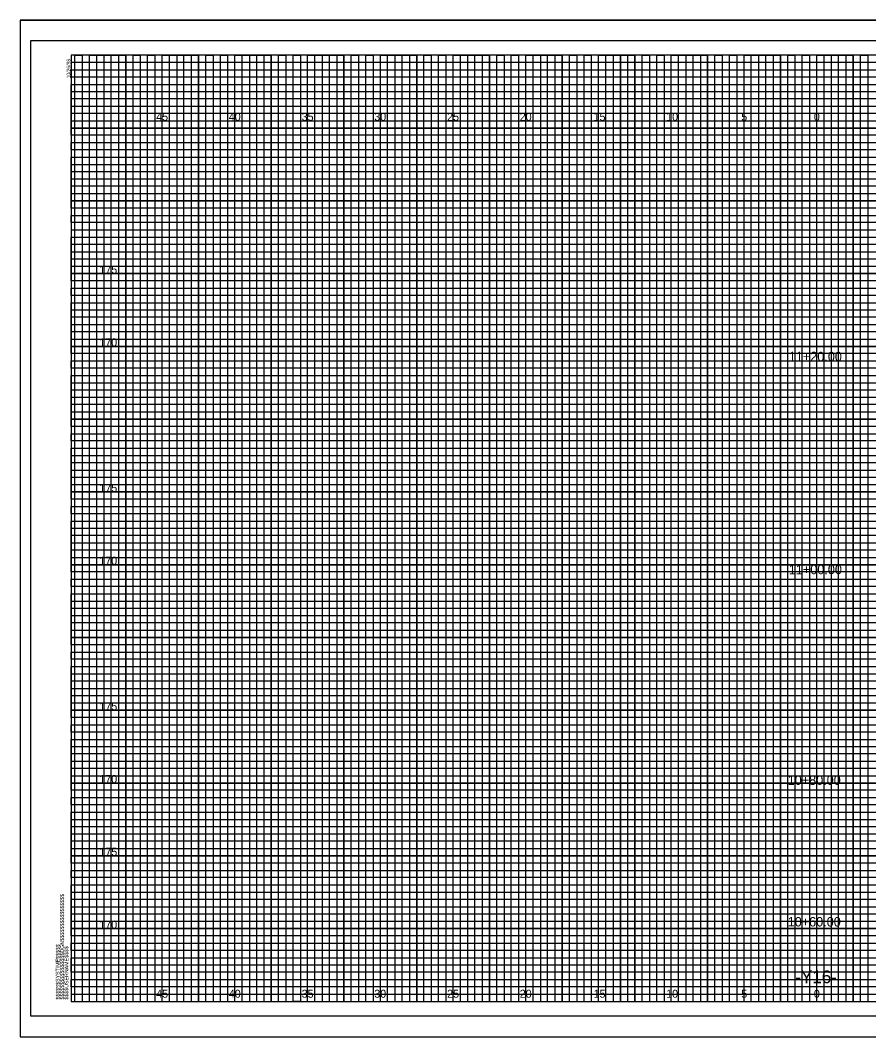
# Model space of a CAD drawing. Extents: x -4 to 103, y -2 to 67.
# Drawn here: x -3.5 to 54.8, y -2.4 to 67.4 of the extents above; entities that cross this region are included whole.
import ezdxf

# ---------------------------------------------------------------- set-up
doc = ezdxf.new("R2010")
doc.units = 0
for name, color, linetype in [('Exist XS Ground Line', 7, 'Continuous'), ('Old_Level_10', 7, 'Continuous'), ('Old_Level_16', 7, 'Continuous'), ('Old_Level_3', 7, 'Continuous'), ('Old_Level_5', 7, 'Continuous'), ('Old_Level_8', 7, 'Continuous'), ('Prop XS Dump Level', 7, 'Continuous'), ('Prop XS EOT Tick Mark', 7, 'Continuous'), ('Prop XS Finish Grade', 7, 'Continuous'), ('Prop XS Side Slope Text', 7, 'Continuous'), ('Prop XS Suitable Common Exc Shape', 7, 'Continuous')]:
    doc.layers.add(name, color=color, linetype=linetype)

msp = doc.modelspace()

# ---------------------------------------------------------------- linework, layer by layer
at = {"layer": 'Exist XS Ground Line'}
msp.add_lwpolyline([(103, 66), (-2.8, 66), (-2.8, -1), (103, -1)], close=True, dxfattribs=at)
at = {"layer": 'Old_Level_10'}
for p, q in [((1.25, 0), (1.25, 65)), ((3.75, 0), (3.75, 65)), ((6.25, 0), (6.25, 65)), ((8.75, 0), (8.75, 65)), ((11.25, 0), (11.25, 65)), ((13.75, 0), (13.75, 65)), ((16.25, 0), (16.25, 65)), ((18.75, 0), (18.75, 65)), ((21.25, 0), (21.25, 65)), ((23.75, 0), (23.75, 65)), ((26.25, 0), (26.25, 65)), ((28.75, 0), (28.75, 65)), ((31.25, 0), (31.25, 65)), ((33.75, 0), (33.75, 65)), ((36.25, 0), (36.25, 65)), ((38.75, 0), (38.75, 65)), ((41.25, 0), (41.25, 65)), ((43.75, 0), (43.75, 65)), ((46.25, 0), (46.25, 65)), ((48.75, 0), (48.75, 65)), ((51.25, 0), (51.25, 65)), ((53.75, 0), (53.75, 65)), ((0, 62.5), (74.25, 62.5)), ((0, 60), (102.5, 60)), ((0, 57.5), (102.5, 57.5)), ((0, 55), (102.5, 55)), ((0, 52.5), (102.5, 52.5)), ((0, 50), (102.5, 50)), ((0, 47.5), (102.5, 47.5)), ((0, 45), (102.5, 45)), ((0, 42.5), (102.5, 42.5)), ((0, 40), (102.5, 40)), ((0, 37.5), (102.5, 37.5)), ((0, 35), (102.5, 35)), ((0, 32.5), (102.5, 32.5)), ((0, 30), (102.5, 30)), ((0, 27.5), (102.5, 27.5)), ((0, 25), (102.5, 25)), ((0, 22.5), (102.5, 22.5)), ((0, 20), (102.5, 20)), ((0, 17.5), (102.5, 17.5)), ((0, 15), (102.5, 15)), ((0, 12.5), (102.5, 12.5)), ((0, 10), (102.5, 10)), ((0, 7.5), (102.5, 7.5)), ((0, 5), (102.5, 5)), ((0, 2.5), (102.5, 2.5))]:
    msp.add_line(p, q, dxfattribs=at)
at = {"layer": 'Old_Level_3'}
for p, q in [((-3.5, 67.4), (103.4, 67.4)), ((-3.5, 67.4), (-3.5, -2.425)), ((-3.5, -2.425), (102.1625, -2.425))]:
    msp.add_line(p, q, dxfattribs=at)
at = {"layer": 'Old_Level_5'}
msp.add_lwpolyline([(103.4, 67.4), (-3.5, 67.4), (-3.5, -2.425), (103.4, -2.425)], close=True, dxfattribs=at)
at = {"layer": 'Old_Level_8'}
for points in [[(1.25, 0), (1.25, 65), (3.75, 65), (3.75, 0), (6.25, 0), (6.25, 65), (8.75, 65), (8.75, 0), (11.25, 0), (11.25, 65), (13.75, 65), (13.75, 0), (16.25, 0), (16.25, 65), (18.75, 65), (18.75, 0), (21.25, 0), (21.25, 65), (23.75, 65), (23.75, 0), (26.25, 0), (26.25, 65), (28.75, 65), (28.75, 0), (31.25, 0), (31.25, 65), (33.75, 65), (33.75, 0), (36.25, 0), (36.25, 65), (38.75, 65), (38.75, 0), (41.25, 0), (41.25, 65), (43.75, 65), (43.75, 0), (46.25, 0), (46.25, 65), (48.75, 65), (48.75, 0), (51.25, 0), (51.25, 65), (53.75, 65), (53.75, 0)], [(102.5, 60), (0, 60), (0, 62.5), (74.25, 62.5)], [(102.5, 55), (0, 55), (0, 57.5), (102.5, 57.5)], [(102.5, 50), (0, 50), (0, 52.5), (102.5, 52.5)], [(102.5, 45), (0, 45), (0, 47.5), (102.5, 47.5)], [(102.5, 40), (0, 40), (0, 42.5), (102.5, 42.5)], [(102.5, 35), (0, 35), (0, 37.5), (102.5, 37.5)], [(102.5, 30), (0, 30), (0, 32.5), (102.5, 32.5)], [(102.5, 25), (0, 25), (0, 27.5), (102.5, 27.5)], [(102.5, 20), (0, 20), (0, 22.5), (102.5, 22.5)], [(102.5, 15), (0, 15), (0, 17.5), (102.5, 17.5)], [(102.5, 10), (0, 10), (0, 12.5), (102.5, 12.5)], [(102.5, 5), (0, 5), (0, 7.5), (102.5, 7.5)], [(0, 2.5), (102.5, 2.5)]]:
    msp.add_lwpolyline(points, dxfattribs=at)
at = {"layer": 'Prop XS Dump Level'}
for p, q in [((0, 0), (0, 0)), ((0, 0), (0, 0)), ((-3.5, -2.425), (103.4, -2.425))]:
    msp.add_line(p, q, dxfattribs=at)
msp.add_lwpolyline([(102.5, 65), (0, 65), (0, 0), (102.5, 0)], close=True, dxfattribs=at)
at = {"layer": 'Prop XS Finish Grade'}
for points in [[(0.25, 0), (0.25, 65), (0.75, 65), (0.75, 0), (1.75, 0), (1.75, 65), (2.25, 65), (2.25, 0), (2.75, 0), (2.75, 65), (3.25, 65), (3.25, 0), (4.25, 0), (4.25, 65), (4.75, 65), (4.75, 0), (5.25, 0), (5.25, 65), (5.75, 65), (5.75, 0), (6.75, 0), (6.75, 65), (7.25, 65), (7.25, 0), (7.75, 0), (7.75, 65), (8.25, 65), (8.25, 0), (9.25, 0), (9.25, 65), (9.75, 65), (9.75, 0), (10.25, 0), (10.25, 65), (10.75, 65), (10.75, 0), (11.75, 0), (11.75, 65), (12.25, 65), (12.25, 0), (12.75, 0), (12.75, 65), (13.25, 65), (13.25, 0), (14.25, 0), (14.25, 65), (14.75, 65), (14.75, 0), (15.75, 0), (15.25, 0), (15.25, 65), (15.75, 65), (15.75, 0), (16.75, 0), (16.75, 65), (17.25, 65), (17.25, 0), (17.75, 0), (17.75, 65), (18.25, 65), (18.25, 0), (19.25, 0), (19.25, 65), (19.75, 65), (19.75, 0), (20.25, 0), (20.25, 65), (20.75, 65), (20.75, 0), (21.75, 0), (21.75, 65), (22.25, 65), (22.25, 0), (22.75, 0), (22.75, 65), (23.25, 65), (23.25, 0), (24.25, 0), (24.25, 65), (24.75, 65), (24.75, 0), (25.25, 0), (25.25, 65), (25.75, 65), (25.75, 0), (26.75, 0), (26.75, 65), (27.25, 65), (27.25, 0), (27.75, 0), (27.75, 65), (28.25, 65), (28.25, 0), (29.25, 0), (29.25, 65), (29.75, 65), (29.75, 0), (30.25, 0), (30.25, 65), (30.75, 65), (30.75, 0)], [(30.75, 0), (31.75, 0), (31.75, 65), (32.25, 65), (32.25, 0), (32.75, 0), (32.75, 65), (33.25, 65), (33.25, 0), (34.25, 0), (34.25, 65), (34.75, 65), (34.75, 0), (35.25, 0), (35.25, 65), (35.75, 65), (35.75, 0), (36.75, 0), (36.75, 65), (37.25, 65), (37.25, 0), (37.75, 0), (37.75, 65), (37.75, 0)], [(38.25, 65), (38.25, 0), (39.25, 0), (39.25, 65), (39.75, 65), (39.75, 0), (40.25, 0), (40.25, 65), (40.75, 65), (40.75, 0), (41.75, 0), (41.75, 65), (42.25, 65), (42.25, 0), (42.75, 0), (42.75, 65), (43.25, 65), (43.25, 0), (43.75, 0), (44.25, 0), (44.25, 65), (44.75, 65), (44.75, 0), (45.25, 0), (45.25, 65), (45.75, 65), (45.75, 0), (46.75, 0), (46.75, 65), (47.25, 65), (47.25, 0), (47.75, 0), (47.75, 65), (48.25, 65), (48.25, 0), (49.25, 0), (49.25, 65), (49.75, 65), (49.75, 0), (50.25, 0), (50.25, 65), (50.75, 65), (50.75, 0), (51.75, 0), (51.75, 65), (52.25, 65), (52.25, 0), (52.75, 0), (52.75, 65), (53.25, 65), (53.25, 0), (54.25, 0), (54.25, 65), (54.75, 65), (54.75, 0), (55.25, 0)], [(0, 62), (0, 63), (74.25, 63), (74.25, 63.5), (0, 63.5), (0, 64), (74.25, 64), (74.25, 64.5), (0, 64.5)], [(102.5, 62), (0, 62)], [(102.5, 61), (0, 61), (0, 61.5), (102.5, 61.5)], [(102.5, 59.5), (0, 59.5), (0, 60.5), (102.5, 60.5)], [(102.5, 58.5), (0, 58.5), (0, 59), (102.5, 59)], [(102.5, 57), (0, 57), (0, 58), (102.5, 58)], [(102.5, 56), (0, 56), (0, 56.5), (102.5, 56.5)], [(102.5, 54.5), (0, 54.5), (0, 55.5), (102.5, 55.5)], [(102.5, 53.5), (0, 53.5), (0, 54), (102.5, 54)], [(0, 53), (102.5, 53)], [(102.5, 52), (0, 52)], [(102.5, 51), (0, 51), (0, 51.5), (102.5, 51.5)], [(102.5, 49.5), (0, 49.5), (0, 50.5), (102.5, 50.5)], [(102.5, 48.5), (0, 48.5), (0, 49), (102.5, 49)], [(102.5, 47), (0, 47), (0, 48), (102.5, 48)], [(102.5, 46), (0, 46), (0, 46.5), (102.5, 46.5)], [(102.5, 44.5), (0, 44.5), (0, 45.5), (102.5, 45.5)], [(102.5, 43.5), (0, 43.5), (0, 44), (102.5, 44)], [(102.5, 42), (0, 42), (0, 43), (102.5, 43)], [(102.5, 41), (0, 41), (0, 41.5), (102.5, 41.5)], [(102.5, 39.5), (0, 39.5), (0, 40.5), (102.5, 40.5)], [(102.5, 38.5), (0, 38.5), (0, 39), (102.5, 39)], [(102.5, 37), (0, 37), (0, 38), (102.5, 38)], [(102.5, 36), (0, 36), (0, 36.5), (102.5, 36.5)], [(102.5, 34.5), (0, 34.5), (0, 35.5), (102.5, 35.5)], [(102.5, 33.5), (0, 33.5), (0, 34), (102.5, 34)], [(102.5, 32), (0, 32), (0, 33), (102.5, 33)], [(102.5, 31), (0, 31), (0, 31.5)], [(0, 31.5), (102.5, 31.5)], [(102.5, 29.5), (0, 29.5), (0, 30.5), (102.5, 30.5)], [(102.5, 28.5), (0, 28.5), (0, 29), (102.5, 29)], [(102.5, 27), (0, 27), (0, 28), (102.5, 28)], [(102.5, 26), (0, 26), (0, 26.5), (102.5, 26.5)], [(102.5, 24.5), (0, 24.5), (0, 25.5), (102.5, 25.5)], [(102.5, 23.5), (0, 23.5), (0, 24), (102.5, 24)], [(102.5, 22), (0, 22), (0, 23), (102.5, 23)], [(102.5, 21), (0, 21), (0, 21.5), (102.5, 21.5)], [(102.5, 19.5), (0, 19.5), (0, 20.5), (102.5, 20.5)], [(102.5, 18.5), (0, 18.5), (0, 19), (102.5, 19)], [(102.5, 17), (0, 17), (0, 18), (102.5, 18)], [(102.5, 16), (0, 16), (0, 16.5), (102.5, 16.5)], [(102.5, 14.5), (0, 14.5), (0, 15.5), (102.5, 15.5)], [(102.5, 13.5), (0, 13.5), (0, 14), (102.5, 14)], [(102.5, 12), (0, 12), (0, 13), (102.5, 13)], [(102.5, 11), (0, 11), (0, 11.5), (102.5, 11.5)], [(102.5, 9.5), (0, 9.5), (0, 10.5), (102.5, 10.5)], [(102.5, 8.5), (0, 8.5), (0, 9), (102.5, 9)], [(102.5, 7), (0, 7), (0, 8), (102.5, 8)], [(102.5, 6), (0, 6), (0, 6.5), (102.5, 6.5)], [(102.5, 4.5), (0, 4.5), (0, 5.5), (102.5, 5.5)], [(102.5, 3.5), (0, 3.5), (0, 4), (102.5, 4)], [(102.5, 2), (0, 2), (0, 3), (102.5, 3)], [(102.5, 1), (0, 1), (0, 1.5), (102.5, 1.5)], [(0, 0.5), (102.5, 0.5)]]:
    msp.add_lwpolyline(points, dxfattribs=at)

# ---------------------------------------------------------------- texts
at = {"layer": 'Old_Level_16'}
for s, p in [('45', (5.8399, 60.5)), ('40', (10.8313, 60.5)), ('35', (15.8399, 60.5)), ('30', (20.8313, 60.5)), ('25', (25.8399, 60.5)), ('20', (30.8313, 60.5)), ('15', (35.9058, 60.5)), ('10', (40.8971, 60.5)), ('5', (46.0574, 60.5)), ('0', (51.0488, 60.5)), ('0', (51.0488, 60.5)), ('45', (5.8399, 0.25)), ('40', (10.8313, 0.25)), ('35', (15.8399, 0.25)), ('30', (20.8313, 0.25)), ('25', (25.8399, 0.25)), ('20', (30.8313, 0.25)), ('15', (35.9058, 0.25)), ('10', (40.8971, 0.25)), ('5', (46.0574, 0.25)), ('0', (51.0488, 0.25)), ('0', (51.0488, 0.25))]:
    msp.add_text(s, height=0.55, dxfattribs=at).set_placement(p)
at = {"layer": 'Old_Level_8'}
msp.add_text('040397', height=0.0025, rotation=90, dxfattribs=at).set_placement((-0.0007, 64.9864))
at = {"layer": 'Prop XS Dump Level'}
for s, height, p in [('10/26/98', 0.25, (-0.0625, 63.4095)), ('$$$$$$$$$$$$$$$$DGN$$$$$$$$$$$$$$$$', 0.2625, (-0.5, 0.125)), ('$$$$$$SYSTIME$$$$$', 0.2625, (-0.7973, 0.1247)), ('$$$$USERNAME$$$$', 0.2625, (-0.2, 0.125))]:
    msp.add_text(s, height=height, rotation=90, dxfattribs=at).set_placement(p)
at = {"layer": 'Prop XS EOT Tick Mark'}
msp.add_text('-Y16-', height=0.875, dxfattribs=at).set_placement((49.7731, 1.25))
at = {"layer": 'Prop XS Side Slope Text'}
for s, p in [('11+20.00', (49.3286, 43.9781)), ('11+00.00', (49.3286, 29.3461)), ('10+80.00', (49.2508, 14.8735)), ('10+60.00', (49.2508, 5.1448))]:
    msp.add_text(s, height=0.65, dxfattribs=at).set_placement(p)
at = {"layer": 'Prop XS Suitable Common Exc Shape'}
for s, p in [('175', (1.9383, 50)), ('170', (1.9296, 45)), ('175', (1.9383, 35)), ('170', (1.9296, 30)), ('175', (1.9383, 20)), ('170', (1.9296, 15)), ('175', (1.9383, 10)), ('170', (1.9296, 5))]:
    msp.add_text(s, height=0.55, dxfattribs=at).set_placement(p)

doc.saveas('drawing.dxf')
